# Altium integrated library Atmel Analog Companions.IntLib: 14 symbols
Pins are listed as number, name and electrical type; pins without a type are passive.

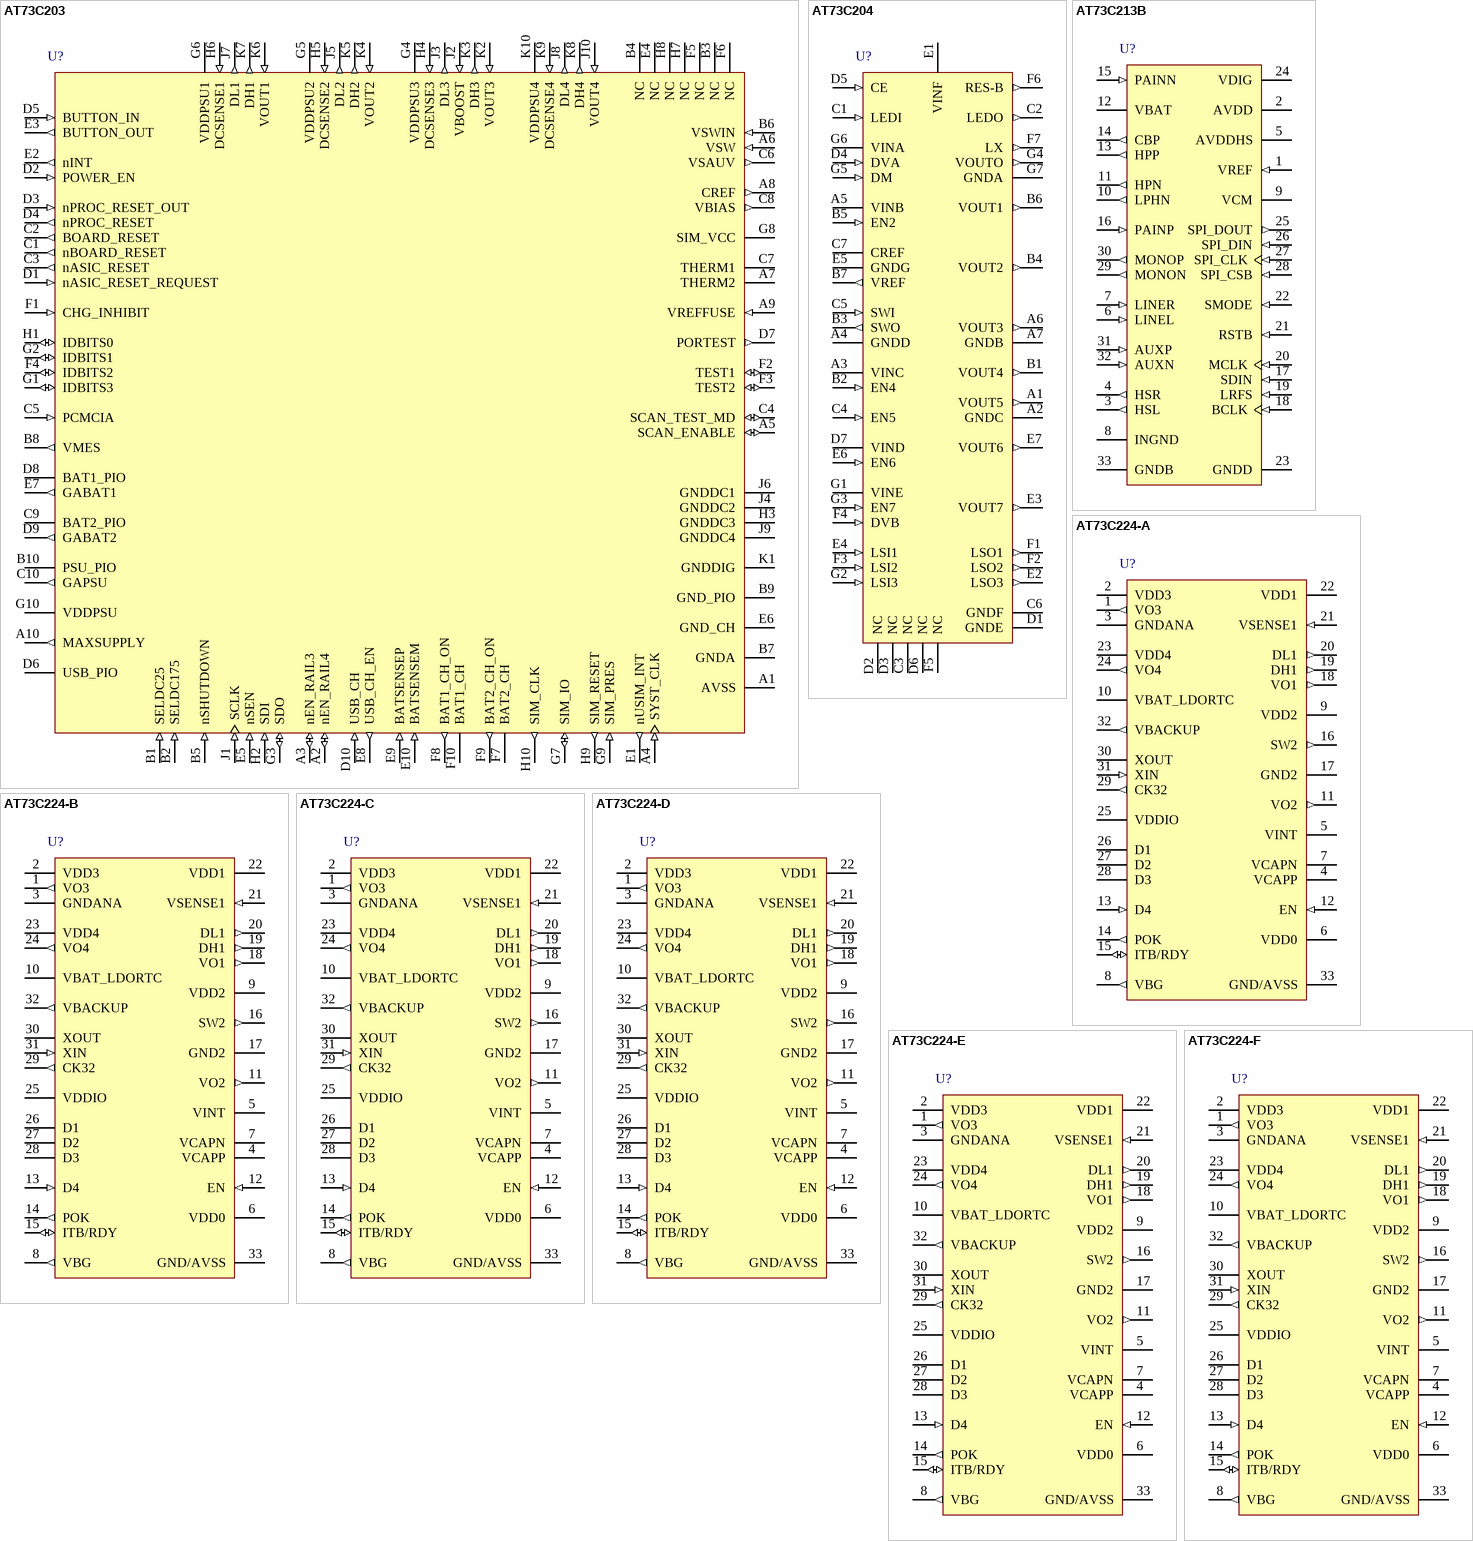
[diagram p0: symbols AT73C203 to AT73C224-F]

## AT73C203
designator U?
Power Management IC for Datacom Platforms, TFBGA100 Pkg
footprint TFBGA100 (BGA, 100-Leads, Body 9x9mm, Pitch 0.8mm)
pins: A1 AVSS (power), A2 nEN_RAIL4 (io), A3 nEN_RAIL3 (io), A4 SYST_CLK (in), A5 SCAN_ENABLE (io), A6 VSW (in), A7 THERM2, A8 CREF (out), A9 VREFFUSE (in), A10 MAXSUPPLY (out), B1 SELDC25 (in), B2 SELDC175 (in), B3 NC, B4 NC, B5 nSHUTDOWN (in), B6 VSWIN (in), B7 GNDA (power), B8 VMES (out), B9 GND_PIO (power), B10 PSU_PIO (power), C1 nBOARD_RESET (out), C2 BOARD_RESET (out), C3 nASIC_RESET (out), C4 SCAN_TEST_MD (io), C5 PCMCIA (in), C6 VSAUV (out), C7 THERM1, C8 VBIAS (out), C9 BAT2_PIO (power), C10 GAPSU (out), D1 nASIC_RESET_REQUEST (in), D2 POWER_EN (in), D3 nPROC_RESET_OUT (in), D4 nPROC_RESET (out), D5 BUTTON_IN (in), D6 USB_PIO (power), D7 PORTEST (out), D8 BAT1_PIO (power), D9 GABAT2 (out), D10 USB_CH (in), E1 nUSIM_INT (out), E2 nINT (out), E3 BUTTON_OUT (out), E4 NC, E5 nSEN (in), E6 GND_CH (power), E7 GABAT1 (out), E8 USB_CH_EN (out), E9 BATSENSEP (in), E10 BATSENSEM (in), F1 CHG_INHIBIT (in), F2 TEST1 (io), F3 TEST2 (io), F4 IDBITS2 (io), F5 NC, F6 NC, F7 BAT2_CH (power), F8 BAT1_CH_ON (out), F9 BAT2_CH_ON (out), F10 BAT1_CH (power), G1 IDBITS3 (io), G2 IDBITS1 (io), G3 SDO (io), G4 VDDPSU3 (power), G5 VDDPSU2 (power), G6 VDDPSU1 (power), G7 SIM_IO (io), G8 SIM_VCC (power), G9 SIM_PRES (in), G10 VDDPSU (power), H1 IDBITS0 (io), H2 SDI (in), H3 GNDDC3 (power), H4 DCSENSE3 (in), H5 DCSENSE2 (in), H6 DCSENSE1 (in), H7 NC, H8 NC, H9 SIM_RESET (out), H10 SIM_CLK (out), J1 SCLK (in), J2 VBOOST (in), J3 DL3 (out), J4 GNDDC2 (power), J5 DL2 (out), J6 GNDDC1 (power), J7 DL1 (out), J8 DL4 (out), J9 GNDDC4 (power), J10 VOUT4 (in), K1 GNDDIG (power), K2 VOUT3 (in), K3 DH3 (out), K4 VOUT2 (in), K5 DH2 (out), K6 VOUT1 (in), K7 DH1 (out), K8 DH4 (out), K9 DCSENSE4 (in), K10 VDDPSU4 (power)

## AT73C204
designator U?
Power Management for Mobiles, TFBGA49 Pkg
footprint TFBGA49 (BGA, 49-Leads, Body 5x5mm, Pitch 0.65mm)
pins: A1 VOUT5 (out), A2 GNDC (power), A3 VINC (power), A4 GNDD (power), A5 VINB (power), A6 VOUT3 (out), A7 GNDB (power), B1 VOUT4 (out), B2 EN4 (in), B3 SWO (out), B4 VOUT2 (out), B5 EN2 (in), B6 VOUT1 (out), B7 VREF (out), C1 LEDI (in), C2 LEDO (out), C3 NC, C4 EN5 (in), C5 SWI (in), C6 GNDF (power), C7 CREF, D1 GNDE (power), D2 NC, D3 NC, D4 DVA (in), D5 CE (in), D6 NC, D7 VIND (power), E1 VINF (power), E2 LSO3 (out), E3 VOUT7 (out), E4 LSI1 (in), E5 GNDG (power), E6 EN6 (in), E7 VOUT6 (out), F1 LSO1 (out), F2 LSO2 (out), F3 LSI2 (in), F4 DVB (in), F5 NC, F6 RES-B (out), F7 LX (out), G1 VINE (power), G2 LSI3 (in), G3 EN7 (in), G4 VOUTO (out), G5 DM (in), G6 VINA (power), G7 GNDA (power)

## AT73C213B
designator U?
Stereo Audio DAC and Audio Power Amplifier Circuit for Battery Powered Handheld Devices, QFN32 Pkg
footprint QFN-32_N (QFN, 32-Leads, Body 7x7 mm, Pitch 0.65mm, IPC Medium Density)
footprint QFN-32_L (QFN, 32-Leads, Body 7x7 mm, Pitch 0.65mm, IPC High Density)
footprint QFN-32_M (QFN, 32-Leads, Body 7x7 mm, Pitch 0.65mm, IPC Low Density)
pins: 1 VREF (in), 2 AVDD (power), 3 HSL (out), 4 HSR (out), 5 AVDDHS (power), 6 LINEL (in), 7 LINER (in), 8 INGND (power), 9 VCM, 10 LPHN (out), 11 HPN (out), 12 VBAT (power), 13 HPP (out), 14 CBP (out), 15 PAINN (in), 16 PAINP (in), 17 SDIN (in), 18 BCLK (in), 19 LRFS (in), 20 MCLK (in), 21 RSTB (in), 22 SMODE (in), 23 GNDD (power), 24 VDIG (power), 25 SPI_DOUT (out), 26 SPI_DIN (in), 27 SPI_CLK (in), 28 SPI_CSB (in), 29 MONON (out), 30 MONOP (out), 31 AUXP (in), 32 AUXN (in), 33 GNDB (power)

## AT73C224-A
designator U?
4 Channel Power Supply with DC/DC Boost, BUCK2=1.8V, LDO4=2.8V, LDO3=2.7V, Dynamic Management Mode, QFN32 Pkg
footprint RQFN032_H_N (QFN, 32-Leads, Body 5x5mm, Pitch 0.5mm, IPC Medium Density)
footprint RQFN032_H_L (QFN, 32-Leads, Body 5x5mm, Pitch 0.5mm, IPC High Density)
footprint RQFN032_H_M (QFN, 32-Leads, Body 5x5mm, Pitch 0.5mm, IPC Low Density)
pins: 1 VO3 (out), 2 VDD3 (power), 3 GNDANA (power), 4 VCAPP, 5 VINT (power), 6 VDD0 (power), 7 VCAPN, 8 VBG (out), 9 VDD2 (power), 10 VBAT_LDORTC (power), 11 VO2 (out), 12 EN (in), 13 D4 (in), 14 POK (out), 15 ITB/RDY (io), 16 SW2 (out), 17 GND2 (power), 18 VO1 (out), 19 DH1 (out), 20 DL1 (out), 21 VSENSE1 (in), 22 VDD1 (power), 23 VDD4 (power), 24 VO4 (out), 25 VDDIO (power), 26 D1 (oc), 27 D2 (oc), 28 D3 (oc), 29 CK32 (out), 30 XOUT, 31 XIN (in), 32 VBACKUP (out), 33 GND/AVSS (power)

## AT73C224-B
designator U?
4 Channel Power Supply with DC/DC Boost, BUCK2=1.2V, LDO4=1.8V, LDO3=1.7V, Dynamic Management Mode, QFN32 Pkg
footprint RQFN032_H_N (QFN, 32-Leads, Body 5x5mm, Pitch 0.5mm, IPC Medium Density)
footprint RQFN032_H_L (QFN, 32-Leads, Body 5x5mm, Pitch 0.5mm, IPC High Density)
footprint RQFN032_H_M (QFN, 32-Leads, Body 5x5mm, Pitch 0.5mm, IPC Low Density)
pins: 1 VO3 (out), 2 VDD3 (power), 3 GNDANA (power), 4 VCAPP, 5 VINT (power), 6 VDD0 (power), 7 VCAPN, 8 VBG (out), 9 VDD2 (power), 10 VBAT_LDORTC (power), 11 VO2 (out), 12 EN (in), 13 D4 (in), 14 POK (out), 15 ITB/RDY (io), 16 SW2 (out), 17 GND2 (power), 18 VO1 (out), 19 DH1 (out), 20 DL1 (out), 21 VSENSE1 (in), 22 VDD1 (power), 23 VDD4 (power), 24 VO4 (out), 25 VDDIO (power), 26 D1 (oc), 27 D2 (oc), 28 D3 (oc), 29 CK32 (out), 30 XOUT, 31 XIN (in), 32 VBACKUP (out), 33 GND/AVSS (power)

## AT73C224-C
designator U?
4 Channel Power Supply with DC/DC Boost, LDO4=2.8V, BUCK2=1.8V, LDO3=2.7V, Dynamic Management Mode, QFN32 Pkg
footprint RQFN032_H_N (QFN, 32-Leads, Body 5x5mm, Pitch 0.5mm, IPC Medium Density)
footprint RQFN032_H_L (QFN, 32-Leads, Body 5x5mm, Pitch 0.5mm, IPC High Density)
footprint RQFN032_H_M (QFN, 32-Leads, Body 5x5mm, Pitch 0.5mm, IPC Low Density)
pins: 1 VO3 (out), 2 VDD3 (power), 3 GNDANA (power), 4 VCAPP, 5 VINT (power), 6 VDD0 (power), 7 VCAPN, 8 VBG (out), 9 VDD2 (power), 10 VBAT_LDORTC (power), 11 VO2 (out), 12 EN (in), 13 D4 (in), 14 POK (out), 15 ITB/RDY (io), 16 SW2 (out), 17 GND2 (power), 18 VO1 (out), 19 DH1 (out), 20 DL1 (out), 21 VSENSE1 (in), 22 VDD1 (power), 23 VDD4 (power), 24 VO4 (out), 25 VDDIO (power), 26 D1 (oc), 27 D2 (oc), 28 D3 (oc), 29 CK32 (out), 30 XOUT, 31 XIN (in), 32 VBACKUP (out), 33 GND/AVSS (power)

## AT73C224-D
designator U?
4 Channel Power Supply with DC/DC Boost, LDO4=1.8V, BUCK2=1.2V, LDO3=1.8V, Dynamic Management Mode, QFN32 Pkg
footprint RQFN032_H_N (QFN, 32-Leads, Body 5x5mm, Pitch 0.5mm, IPC Medium Density)
footprint RQFN032_H_L (QFN, 32-Leads, Body 5x5mm, Pitch 0.5mm, IPC High Density)
footprint RQFN032_H_M (QFN, 32-Leads, Body 5x5mm, Pitch 0.5mm, IPC Low Density)
pins: 1 VO3 (out), 2 VDD3 (power), 3 GNDANA (power), 4 VCAPP, 5 VINT (power), 6 VDD0 (power), 7 VCAPN, 8 VBG (out), 9 VDD2 (power), 10 VBAT_LDORTC (power), 11 VO2 (out), 12 EN (in), 13 D4 (in), 14 POK (out), 15 ITB/RDY (io), 16 SW2 (out), 17 GND2 (power), 18 VO1 (out), 19 DH1 (out), 20 DL1 (out), 21 VSENSE1 (in), 22 VDD1 (power), 23 VDD4 (power), 24 VO4 (out), 25 VDDIO (power), 26 D1 (oc), 27 D2 (oc), 28 D3 (oc), 29 CK32 (out), 30 XOUT, 31 XIN (in), 32 VBACKUP (out), 33 GND/AVSS (power)

## AT73C224-E
designator U?
4 Channel Power Supply with DC/DC Boost, BOOST1=5.2V, LDO4=3.3V, LDO3=3V, Dynamic Management Mode, QFN32 Pkg
footprint RQFN032_H_N (QFN, 32-Leads, Body 5x5mm, Pitch 0.5mm, IPC Medium Density)
footprint RQFN032_H_L (QFN, 32-Leads, Body 5x5mm, Pitch 0.5mm, IPC High Density)
footprint RQFN032_H_M (QFN, 32-Leads, Body 5x5mm, Pitch 0.5mm, IPC Low Density)
pins: 1 VO3 (out), 2 VDD3 (power), 3 GNDANA (power), 4 VCAPP, 5 VINT (power), 6 VDD0 (power), 7 VCAPN, 8 VBG (out), 9 VDD2 (power), 10 VBAT_LDORTC (power), 11 VO2 (out), 12 EN (in), 13 D4 (in), 14 POK (out), 15 ITB/RDY (io), 16 SW2 (out), 17 GND2 (power), 18 VO1 (out), 19 DH1 (out), 20 DL1 (out), 21 VSENSE1 (in), 22 VDD1 (power), 23 VDD4 (power), 24 VO4 (out), 25 VDDIO (power), 26 D1 (oc), 27 D2 (oc), 28 D3 (oc), 29 CK32 (out), 30 XOUT, 31 XIN (in), 32 VBACKUP (out), 33 GND/AVSS (power)

## AT73C224-F
designator U?
4 Channel Power Supply with DC/DC Boost, BUCK2=1.8V, LDO4=2.8V, LDO3=2.7V, Static Management Mode, QFN32 Pkg
footprint RQFN032_H_N (QFN, 32-Leads, Body 5x5mm, Pitch 0.5mm, IPC Medium Density)
footprint RQFN032_H_L (QFN, 32-Leads, Body 5x5mm, Pitch 0.5mm, IPC High Density)
footprint RQFN032_H_M (QFN, 32-Leads, Body 5x5mm, Pitch 0.5mm, IPC Low Density)
pins: 1 VO3 (out), 2 VDD3 (power), 3 GNDANA (power), 4 VCAPP, 5 VINT (power), 6 VDD0 (power), 7 VCAPN, 8 VBG (out), 9 VDD2 (power), 10 VBAT_LDORTC (power), 11 VO2 (out), 12 EN (in), 13 D4 (in), 14 POK (out), 15 ITB/RDY (io), 16 SW2 (out), 17 GND2 (power), 18 VO1 (out), 19 DH1 (out), 20 DL1 (out), 21 VSENSE1 (in), 22 VDD1 (power), 23 VDD4 (power), 24 VO4 (out), 25 VDDIO (power), 26 D1 (oc), 27 D2 (oc), 28 D3 (oc), 29 CK32 (out), 30 XOUT, 31 XIN (in), 32 VBACKUP (out), 33 GND/AVSS (power)

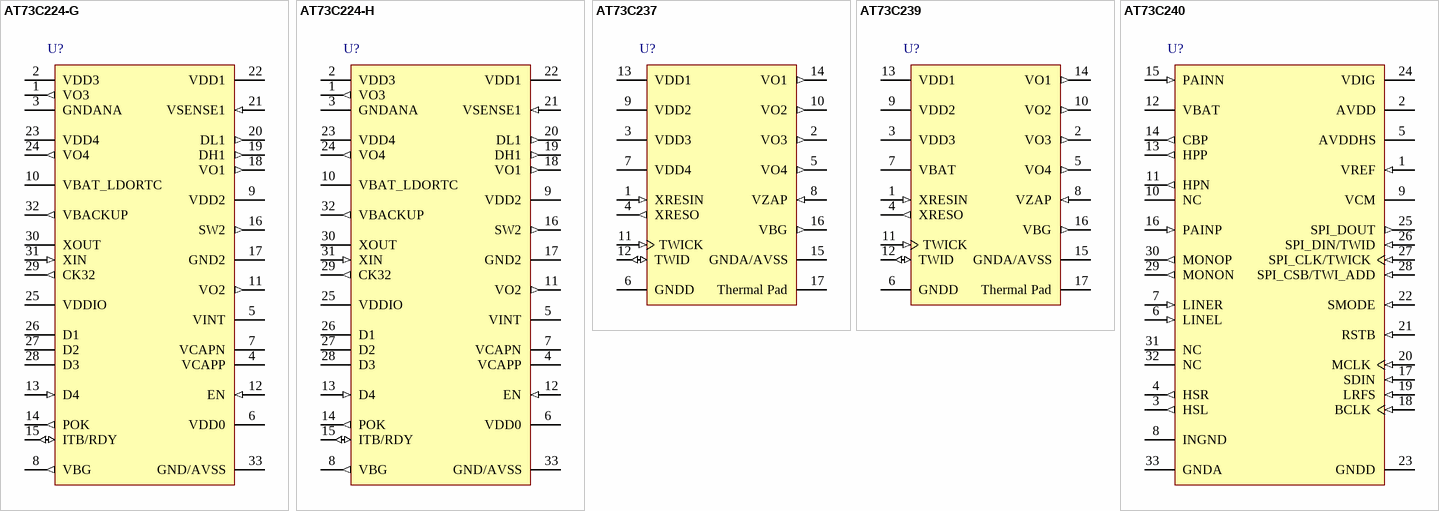
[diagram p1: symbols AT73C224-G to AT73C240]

## AT73C224-G
designator U?
4 Channel Power Supply with DC/DC Boost, LDO4=2.8V, BUCK2=1.8V, LDO3=2.7V, Static Management Mode, QFN32 Pkg
footprint RQFN032_H_N (QFN, 32-Leads, Body 5x5mm, Pitch 0.5mm, IPC Medium Density)
footprint RQFN032_H_L (QFN, 32-Leads, Body 5x5mm, Pitch 0.5mm, IPC High Density)
footprint RQFN032_H_M (QFN, 32-Leads, Body 5x5mm, Pitch 0.5mm, IPC Low Density)
pins: 1 VO3 (out), 2 VDD3 (power), 3 GNDANA (power), 4 VCAPP, 5 VINT (power), 6 VDD0 (power), 7 VCAPN, 8 VBG (out), 9 VDD2 (power), 10 VBAT_LDORTC (power), 11 VO2 (out), 12 EN (in), 13 D4 (in), 14 POK (out), 15 ITB/RDY (io), 16 SW2 (out), 17 GND2 (power), 18 VO1 (out), 19 DH1 (out), 20 DL1 (out), 21 VSENSE1 (in), 22 VDD1 (power), 23 VDD4 (power), 24 VO4 (out), 25 VDDIO (power), 26 D1 (oc), 27 D2 (oc), 28 D3 (oc), 29 CK32 (out), 30 XOUT, 31 XIN (in), 32 VBACKUP (out), 33 GND/AVSS (power)

## AT73C224-H
designator U?
4 Channel Power Supply with DC/DC Boost, BOOST1=5.2V, LDO4=3.3V, LDO3=3V, Static Management Mode, QFN32 Pkg
footprint RQFN032_H_N (QFN, 32-Leads, Body 5x5mm, Pitch 0.5mm, IPC Medium Density)
footprint RQFN032_H_L (QFN, 32-Leads, Body 5x5mm, Pitch 0.5mm, IPC High Density)
footprint RQFN032_H_M (QFN, 32-Leads, Body 5x5mm, Pitch 0.5mm, IPC Low Density)
pins: 1 VO3 (out), 2 VDD3 (power), 3 GNDANA (power), 4 VCAPP, 5 VINT (power), 6 VDD0 (power), 7 VCAPN, 8 VBG (out), 9 VDD2 (power), 10 VBAT_LDORTC (power), 11 VO2 (out), 12 EN (in), 13 D4 (in), 14 POK (out), 15 ITB/RDY (io), 16 SW2 (out), 17 GND2 (power), 18 VO1 (out), 19 DH1 (out), 20 DL1 (out), 21 VSENSE1 (in), 22 VDD1 (power), 23 VDD4 (power), 24 VO4 (out), 25 VDDIO (power), 26 D1 (oc), 27 D2 (oc), 28 D3 (oc), 29 CK32 (out), 30 XOUT, 31 XIN (in), 32 VBACKUP (out), 33 GND/AVSS (power)

## AT73C237
designator U?
4 Channel Power Management Unit for Wireless Modules, QFN16 Pkg
footprint QFN16_N (QFN, 16-Leads, Body 3x3mm, Pitch 0.5mm, IPC Medium Density)
footprint QFN16_L (QFN, 16-Leads, Body 3x3mm, Pitch 0.5mm, IPC High Density)
footprint QFN16_M (QFN, 16-Leads, Body 3x3mm, Pitch 0.5mm, IPC Low Density)
pins: 1 XRESIN (in), 2 VO3 (out), 3 VDD3 (power), 4 XRESO (out), 5 VO4 (out), 6 GNDD (power), 7 VDD4 (power), 8 VZAP (in), 9 VDD2 (power), 10 VO2 (out), 11 TWICK (in), 12 TWID (io), 13 VDD1 (power), 14 VO1 (out), 15 GNDA/AVSS (power), 16 VBG (out), 17 Thermal Pad (power)

## AT73C239
designator U?
4 Channel Power Management Unit for Wireless Modules, QFN16 Pkg
footprint QFN16_N (QFN, 16-Leads, Body 3x3mm, Pitch 0.5mm, IPC Medium Density)
footprint QFN16_L (QFN, 16-Leads, Body 3x3mm, Pitch 0.5mm, IPC High Density)
footprint QFN16_M (QFN, 16-Leads, Body 3x3mm, Pitch 0.5mm, IPC Low Density)
pins: 1 XRESIN (in), 2 VO3 (out), 3 VDD3 (power), 4 XRESO (out), 5 VO4 (out), 6 GNDD (power), 7 VBAT (power), 8 VZAP (in), 9 VDD2 (power), 10 VO2 (out), 11 TWICK (in), 12 TWID (io), 13 VDD1 (power), 14 VO1 (out), 15 GNDA/AVSS (power), 16 VBG (out), 17 Thermal Pad (power)

## AT73C240
designator U?
Stereo Audio DAC and Audio Power Amplifier Circuit for Battery Powered Handheld Devices, QFN32 Pkg
footprint RQFN032_H_N (QFN, 32-Leads, Body 5x5mm, Pitch 0.5mm, IPC Medium Density)
footprint RQFN032_H_L (QFN, 32-Leads, Body 5x5mm, Pitch 0.5mm, IPC High Density)
footprint RQFN032_H_M (QFN, 32-Leads, Body 5x5mm, Pitch 0.5mm, IPC Low Density)
pins: 1 VREF (in), 2 AVDD (power), 3 HSL (out), 4 HSR (out), 5 AVDDHS (power), 6 LINEL (in), 7 LINER (in), 8 INGND (power), 9 VCM, 10 NC, 11 HPN (out), 12 VBAT (power), 13 HPP (out), 14 CBP (out), 15 PAINN (in), 16 PAINP (in), 17 SDIN (in), 18 BCLK (in), 19 LRFS (in), 20 MCLK (in), 21 RSTB (in), 22 SMODE (in), 23 GNDD (power), 24 VDIG (power), 25 SPI_DOUT (out), 26 SPI_DIN/TWID (in), 27 SPI_CLK/TWICK (in), 28 SPI_CSB/TWI_ADD (in), 29 MONON (out), 30 MONOP (out), 31 NC, 32 NC, 33 GNDA (power)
